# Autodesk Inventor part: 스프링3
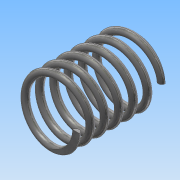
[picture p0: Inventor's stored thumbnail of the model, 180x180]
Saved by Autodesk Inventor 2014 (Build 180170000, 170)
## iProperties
Created: 2019-07
Part Number: 스프링3
Material: 강철, 탄소
Document SubType Name: Modeling
Designer: net
Density: 7.87 g/cm^3
Appearance: 반연마
Mass: 7.79005 g
Surface Area: 20.0872 cm^2
Volume: 0.989841 cm^3
Author: net
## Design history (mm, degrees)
sketch "스케치1"
  geometry: L1 (0, 0)-(8.5, 0); L2 (8.5, 0)-(8.5, 25.33); L3 (8.5, 25.33)-(0, 25.33); L4 (0, 25.33)-(0, 0); C1 r 1 at (8.5, 0)
  constraints: 8 end point, 2 parallel, 1 centre point, 1 coincident, 1 horizontal, 1 perpendicular
  dimensions: "d0" = 17 diameter of L2 L4; "d1" = 25.33013 distance of L1.end L2.end (derived); "d2" = 2 diameter of C1
feature "코일1" pitch "d3" = 10; turns "d5" = 6; dims "d4" = 25.33013 (= d1), "d6" = 0, angle "d7" = 90 deg, angle "d8" = 90 deg, "d9" = 0, "d10" = 0
node "작업 평면1"
node "작업 평면2"
sketch "스케치2"
  geometry: L1 (-1, 0)-(1, 0) reference; 1 further point
  constraints: 1 horizontal alignment
extrude "돌출1" cut sketch "스케치2" stored distance "d13" = 10; taper "d14" = 0 deg
sketch "스케치3"
  geometry: L1 (7.5, 0)-(9.5, 0) reference; 1 further point
  constraints: 1 horizontal alignment
extrude "돌출2" cut sketch "스케치3" stored distance "d15" = 10; taper "d16" = 0 deg
node "솔리드1"
node "절단 모서리 투영1"
node "절단 모서리 투영2"
other parameters: "d11" = 90 deg, "d12" = 90 deg
